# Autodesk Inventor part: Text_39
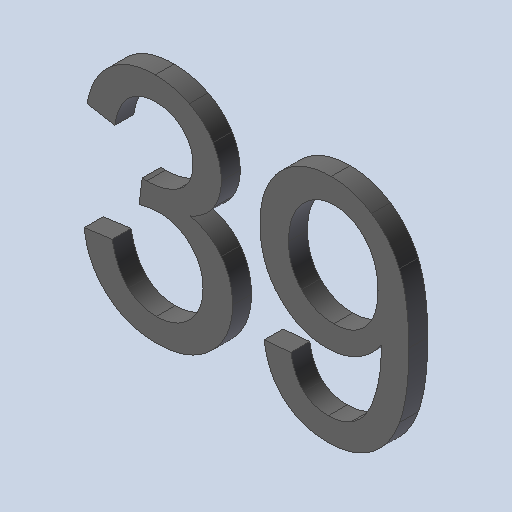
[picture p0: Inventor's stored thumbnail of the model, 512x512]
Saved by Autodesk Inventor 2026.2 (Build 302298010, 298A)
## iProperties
Created: 2026-10
Part Number: Text_39
Material: Générique
Document SubType Name: Modeling
Designer: mel
Density: 1 g/cm^3
Appearance: Par défaut
Author: mel
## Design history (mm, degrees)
feature "Base1"
feature "Base2"
node "Solide1"
node "Solide2"
